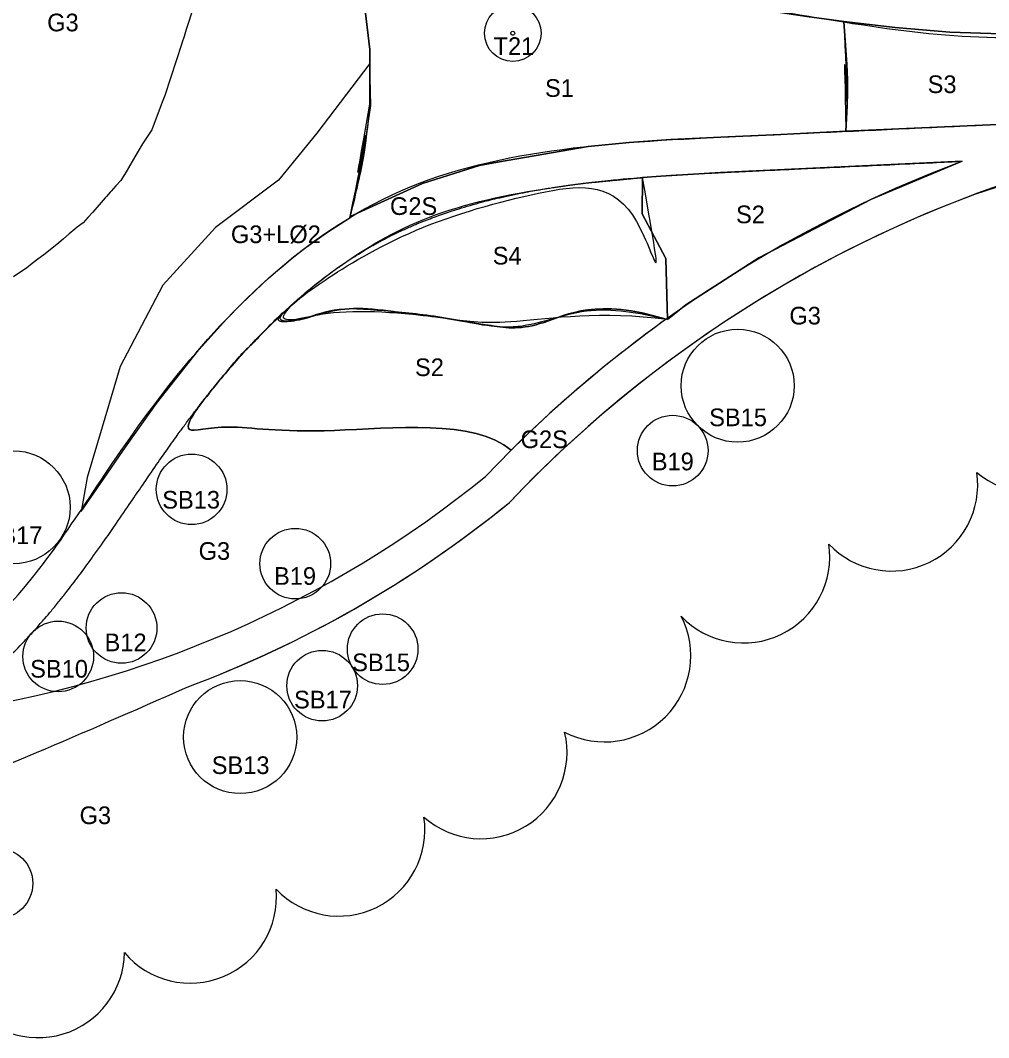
# Model space of a CAD drawing. Extents: x 0 to 512122, y 0 to 6212554.
# Drawn here: x 511501.5 to 511570.1, y 6211310.9 to 6211382.9 of the extents above; entities that cross this region are included whole.
import ezdxf

# ---------------------------------------------------------------- set-up
doc = ezdxf.new("R2010")
doc.units = 0
for name, color, linetype in [('_G3S_Slået græsser', 7, 'Continuous'), ('_LØ2', 7, 'Continuous'), ('_Paths', 7, 'Continuous'), ('_S1_rabarber', 7, 'Continuous'), ('_S2_skovjorbær', 7, 'Continuous'), ('_S3_Mynte', 7, 'Continuous'), ('_S4_Løvstikke', 7, 'Continuous'), ('_Spredmingskorridor_hatch', 7, 'Continuous'), ('Clouds', 7, 'Continuous'), ('Skel', 7, 'Continuous'), ('TV_U_AFM_Symbl_Gul', 7, 'Continuous'), ('TV_U_LYS_Mastenummer', 7, 'Continuous'), ('TV_U_LYS_Nyx330-Trafiksti-x2', 7, 'Continuous')]:
    doc.layers.add(name, color=color, linetype=linetype)

# ---------------------------------------------------------------- blocks, each defined once
blk = doc.blocks.new('SOLITAIRE TREES')
at = {"layer": 'Skel'}
for radius in [2, 0.141]:
    blk.add_circle((0, 0), radius, dxfattribs=at)

msp = doc.modelspace()

# ---------------------------------------------------------------- linework, layer by layer
at = {"layer": '_G3S_Slået græsser'}
msp.add_open_spline([(511577.95, 6211373.42), (511575.884, 6211372.856), (511571.072, 6211371.35), (511569.062, 6211370.609), (511577.95, 6211373.42), (511569.062, 6211370.609)], degree=3, dxfattribs=at)
at = {"layer": '_LØ2'}
msp.add_lwpolyline([(511526.26, 6211379.864), (511522.52, 6211374.951), (511519.801, 6211371.62), (511515.336, 6211368.267), (511511.61, 6211364.186), (511508.601, 6211358.419), (511507.324, 6211354.123), (511506.248, 6211350.554), (511505.835, 6211348.17), (511507.421, 6211350.442), (511508.802, 6211352.488), (511511.168, 6211355.815), (511514.162, 6211359.603), (511516.125, 6211361.774), (511517.188, 6211362.853), (511519.105, 6211364.695), (511520.865, 6211366.19), (511521.56, 6211366.728), (511523.262, 6211367.941), (511524.852, 6211368.956), (511525.365, 6211371.222), (511525.832, 6211373.576), (511526.323, 6211376.898)], close=True, dxfattribs=at)
at = {"layer": '_Paths'}
for centre, radius, start, end in [((511599.913, 6211288.279), 87.92, 104.34684, 136.49474), ((511599.913, 6211288.279), 90.42, 110.54211, 136.3929), ((511599.913, 6211288.279), 87.92, 110.54211, 136.3929), ((511599.913, 6211288.279), 87.92, 110.54211, 136.3929), ((511485.308, 6211411.031), 77.851, 278.00491, 309.13245), ((511485.308, 6211411.031), 80.351, 290.31586, 309.24725), ((511485.308, 6211411.031), 80.351, 290.31926, 309.13245)]:
    msp.add_arc(centre, radius, start, end, dxfattribs=at)
for points in [[(511496.284, 6211337.238), (511497.181, 6211337.983), (511503.211, 6211343.318), (511510.408, 6211356.244), (511526.967, 6211373.541), (511552.416, 6211374.723), (511569.62, 6211375.512), (511577.558, 6211375.876)], [(511496.15, 6211333.938), (511496.382, 6211334.119), (511496.614, 6211334.301), (511497.277, 6211334.827), (511497.707, 6211335.177), (511498.56, 6211335.891), (511498.983, 6211336.255), (511499.609, 6211336.816), (511499.816, 6211337.005), (511500.125, 6211337.293), (511500.227, 6211337.39), (511500.38, 6211337.535), (511500.431, 6211337.584), (511500.533, 6211337.682), (511500.583, 6211337.731), (511501.039, 6211338.174), (511501.432, 6211338.575), (511502.2, 6211339.389), (511502.574, 6211339.802), (511503.305, 6211340.639), (511503.662, 6211341.062), (511504.36, 6211341.916), (511504.702, 6211342.347), (511505.71, 6211343.65), (511506.356, 6211344.531), (511507.619, 6211346.304), (511508.235, 6211347.195), (511509.454, 6211348.976), (511510.058, 6211349.864), (511511.269, 6211351.627), (511511.876, 6211352.5), (511512.804, 6211353.79), (511513.115, 6211354.216), (511513.746, 6211355.061), (511514.065, 6211355.48), (511515.037, 6211356.725), (511515.702, 6211357.539), (511517.067, 6211359.122), (511517.767, 6211359.891), (511519.202, 6211361.371), (511519.937, 6211362.082), (511521.44, 6211363.435), (511522.209, 6211364.077), (511523.78, 6211365.279), (511524.583, 6211365.839), (511525.812, 6211366.612), (511526.226, 6211366.858), (511526.749, 6211367.15), (511526.853, 6211367.208), (511527.011, 6211367.293), (511527.064, 6211367.322), (511527.169, 6211367.378), (511527.222, 6211367.406), (511527.486, 6211367.545), (511527.7, 6211367.653), (511528.344, 6211367.971), (511528.781, 6211368.172), (511529.665, 6211368.555), (511530.114, 6211368.736), (511531.477, 6211369.251), (511532.41, 6211369.557), (511534.317, 6211370.104), (511535.292, 6211370.343), (511537.278, 6211370.766), (511538.289, 6211370.949), (511540.341, 6211371.267), (511541.381, 6211371.402), (511543.485, 6211371.635), (511544.548, 6211371.733), (511546.689, 6211371.901), (511547.767, 6211371.972), (511549.933, 6211372.096), (511551.02, 6211372.151), (511552.38, 6211372.215), (511552.652, 6211372.228), (511553.061, 6211372.247), (511553.197, 6211372.253), (511553.469, 6211372.266), (511553.605, 6211372.272), (511554.285, 6211372.304), (511555.913, 6211372.38), (511557.532, 6211372.455), (511560.757, 6211372.604), (511562.891, 6211372.704), (511566.075, 6211372.852), (511567.131, 6211372.901), (511568.185, 6211372.95)], [(511422.936, 6211366.106), (511424.117, 6211362.932), (511427.915, 6211354.799), (511434.078, 6211340.703), (511442.957, 6211324.941), (511459.145, 6211317.324), (511475.029, 6211321.473), (511492.664, 6211326.687), (511505.824, 6211332.405), (511513.21, 6211335.68)]]:
    msp.add_open_spline(points, degree=3, dxfattribs=at)
at = {"layer": '_S1_rabarber'}
for points in [[(511526.256, 6211376.989), (511526.268, 6211380.857), (511525.432, 6211387.792), (511524.381, 6211399.347), (511527.219, 6211394.835), (511529.727, 6211391.636), (511532.584, 6211388.932), (511535.615, 6211387.042), (511537.588, 6211386.323), (511540.138, 6211385.706), (511542.64, 6211385.314), (511549.961, 6211384.291), (511557.192, 6211383.208), (511559.801, 6211382.854)], [(511559.801, 6211382.854), (511557.192, 6211383.208), (511549.961, 6211384.291), (511542.64, 6211385.314), (511540.138, 6211385.706), (511537.588, 6211386.323), (511535.615, 6211387.042), (511532.584, 6211388.932), (511529.727, 6211391.636), (511527.219, 6211394.835), (511524.381, 6211399.347), (511525.432, 6211387.792), (511526.268, 6211380.857), (511526.256, 6211376.989)], [(511559.953, 6211375.077), (511555.358, 6211374.856), (511551.59, 6211374.681), (511547.568, 6211374.486), (511544.625, 6211374.289), (511541.716, 6211373.999), (511535.288, 6211372.879), (511534.023, 6211372.647), (511529.982, 6211371.369), (511524.867, 6211369.041)], [(511524.867, 6211369.041), (511529.982, 6211371.369), (511534.023, 6211372.647), (511535.288, 6211372.879), (511541.716, 6211373.999), (511544.625, 6211374.289), (511547.568, 6211374.486), (511551.59, 6211374.681), (511555.358, 6211374.856), (511559.953, 6211375.077)]]:
    msp.add_lwpolyline(points, dxfattribs=at)
for points in [[(511559.801, 6211382.854), (511560.066, 6211377.754), (511559.953, 6211375.077), (511559.801, 6211382.854), (511559.953, 6211375.077)], [(511559.953, 6211375.077), (511560.005, 6211375.969), (511560.157, 6211378.563), (511559.942, 6211381.154), (511559.801, 6211382.854)], [(511524.867, 6211369.041), (511525.961, 6211374.32), (511526.256, 6211376.989), (511524.867, 6211369.041), (511526.256, 6211376.989)], [(511526.256, 6211376.989), (511526.172, 6211376.098), (511525.917, 6211373.415), (511525.287, 6211370.792), (511524.867, 6211369.041)]]:
    msp.add_open_spline(points, degree=3, dxfattribs=at)
at = {"layer": '_S2_skovjorbær'}
msp.add_line((511547.231, 6211361.766), (511547.231, 6211361.766), dxfattribs=at)
msp.add_lwpolyline([(511547.214, 6211366.059), (511545.542, 6211369.221), (511545.547, 6211371.8), (511546.852, 6211371.901), (511551.085, 6211372.149), (511568.185, 6211372.95), (511561.763, 6211370.274), (511553.78, 6211366.124), (511548.622, 6211362.784), (511547.326, 6211361.742), (511547.214, 6211366.059)], dxfattribs=at)
msp.add_lwpolyline([(511547.326, 6211361.742), (511548.622, 6211362.784), (511553.78, 6211366.124), (511561.763, 6211370.274), (511568.185, 6211372.95), (511551.085, 6211372.149), (511546.852, 6211371.901), (511545.547, 6211371.8), (511545.542, 6211369.221), (511547.214, 6211366.059)], close=True, dxfattribs=at)
msp.add_arc((511599.913, 6211288.279), 90.42, 125.63628, 134.75422, dxfattribs=at)
msp.add_arc((511599.913, 6211288.279), 90.42, 125.63628, 134.75422, dxfattribs=at)
for points in [[(511547.231, 6211361.766), (511542.358, 6211363.29), (511538.022, 6211360.885), (511534.945, 6211361.269), (511531.26, 6211361.927), (511528.768, 6211362.168), (511525.608, 6211362.662), (511523.32, 6211362.361), (511521.384, 6211361.687), (511519.995, 6211361.557), (511519.62, 6211361.679), (511519.945, 6211362.066)], [(511519.945, 6211362.066), (511519.62, 6211361.679), (511519.995, 6211361.557), (511521.384, 6211361.687), (511523.32, 6211362.361), (511525.608, 6211362.662), (511528.768, 6211362.168), (511531.26, 6211361.927), (511534.945, 6211361.269), (511538.022, 6211360.885), (511542.358, 6211363.29), (511547.231, 6211361.766)], [(511519.945, 6211362.066), (511519.1, 6211361.199), (511518.127, 6211360.26), (511517.701, 6211359.775), (511517.257, 6211359.421), (511516.044, 6211357.948), (511515.353, 6211357.112), (511515.015, 6211356.704), (511514.781, 6211356.368), (511514.137, 6211355.639), (511512.739, 6211353.417), (511515.839, 6211354.508), (511521.755, 6211353.372), (511533.688, 6211354.725), (511536.251, 6211352.489)], [(511536.251, 6211352.489), (511533.688, 6211354.725), (511521.755, 6211353.372), (511515.839, 6211354.508), (511512.739, 6211353.417), (511514.137, 6211355.639), (511514.781, 6211356.368), (511515.015, 6211356.704), (511515.353, 6211357.112), (511516.044, 6211357.948), (511517.257, 6211359.421), (511517.701, 6211359.775), (511518.127, 6211360.26), (511519.1, 6211361.199), (511519.945, 6211362.066)]]:
    msp.add_open_spline(points, degree=3, dxfattribs=at)
at = {"layer": '_S3_Mynte'}
msp.add_lwpolyline([(511573.351, 6211381.998), (511570.939, 6211381.975), (511567.316, 6211382.1), (511563.441, 6211382.432), (511559.802, 6211382.849), (511560.022, 6211379.806), (511560.059, 6211378.724), (511560.065, 6211377.836), (511560.047, 6211376.868), (511559.954, 6211375.075), (511571.776, 6211375.611)], dxfattribs=at)
msp.add_lwpolyline([(511571.776, 6211375.611), (511559.954, 6211375.075), (511560.047, 6211376.868), (511560.065, 6211377.836), (511560.059, 6211378.724), (511560.022, 6211379.806), (511559.802, 6211382.849), (511563.441, 6211382.432), (511567.316, 6211382.1), (511570.939, 6211381.975), (511573.351, 6211381.998)], close=True, dxfattribs=at)
at = {"layer": '_S4_Løvstikke'}
for points in [[(511545.547, 6211371.804), (511545.542, 6211369.224), (511547.214, 6211366.062)], [(511545.547, 6211371.8), (511545.542, 6211369.224), (511547.214, 6211366.062), (511547.326, 6211361.745)], [(511547.214, 6211366.062), (511547.326, 6211361.745)]]:
    msp.add_lwpolyline(points, dxfattribs=at)
for points, degree in [([(511547.326, 6211361.745), (511542.618, 6211362.374), (511535.415, 6211361.239), (511532.11, 6211361.782), (511527.621, 6211362.325), (511523.379, 6211362.325), (511521.06, 6211361.683), (511519.793, 6211361.702), (511520.66, 6211362.734), (511522.197, 6211364.046), (511529.106, 6211368.337), (511538.627, 6211371.004), (511545.552, 6211371.801), (511547.326, 6211361.745), (511545.552, 6211371.801)], 3), ([(511538.627, 6211371.004), (511540.912, 6211371.354), (511543.23, 6211371.577), (511545.547, 6211371.8)], 2), ([(511547.326, 6211361.745), (511545.755, 6211362.096), (511541.773, 6211362.987), (511536.719, 6211360.638), (511531.712, 6211361.972), (511527.809, 6211362.298), (511523.743, 6211362.693), (511521.752, 6211361.708), (511519.198, 6211361.456), (511521.025, 6211363.052), (511523.443, 6211365.161), (511529.589, 6211369.132), (511535.383, 6211370.506), (511538.627, 6211371.004)], 3)]:
    msp.add_open_spline(points, degree=degree, dxfattribs=at)
at = {"layer": '_Spredmingskorridor_hatch'}
msp.add_open_spline([(511467.291, 6211448.868), (511473.268, 6211448.326), (511486.519, 6211446.703), (511493.234, 6211420.769), (511520.952, 6211413.243), (511528.733, 6211386.924), (511552.285, 6211384.428), (511571.21, 6211380.366), (511589.487, 6211384.409), (511596.578, 6211388.532), (511598.184, 6211389.583)], degree=3, dxfattribs=at)
at = {"layer": 'Clouds'}
for centre, start, end in [((511573.169, 6211355.57), 229.63626, 14.63626), ((511563.182, 6211350.04), 223.30717, 8.30717), ((511552.71, 6211344.952), 223.52549, 8.52549), ((511542.872, 6211337.943), 242.40351, 27.40351), ((511534.119, 6211331.095), 228.67799, 13.67799), ((511524.057, 6211325.614), 223.47784, 8.47784), ((511513.555, 6211320.868), 220.16545, 5.16545), ((511502.794, 6211317.009), 214.28131, 359.28131)]:
    msp.add_arc(centre, 6.1, start, end, dxfattribs=at)
at = {"layer": 'TV_U_LYS_Mastenummer'}
for centre, radius in [((511552.291, 6211357.065), 4), ((511552.291, 6211357.065), 4), ((511547.695, 6211352.469), 2.5), ((511547.695, 6211352.469), 2.5), ((511501.05, 6211348.456), 4), ((511513.649, 6211349.728), 2.5), ((511520.982, 6211344.465), 2.5), ((511508.686, 6211339.912), 2.5), ((511504.204, 6211337.898), 2.5), ((511504.204, 6211337.898), 2.5), ((511527.168, 6211338.414), 2.5), ((511527.168, 6211338.414), 2.5), ((511522.887, 6211335.828), 2.5), ((511522.887, 6211335.828), 2.5), ((511517.083, 6211332.189), 4), ((511499.901, 6211321.829), 2.5)]:
    msp.add_circle(centre, radius, dxfattribs=at)
at = {"layer": 'TV_U_LYS_Nyx330-Trafiksti-x2'}
msp.add_lwpolyline([(511513.788, 6211383.886), (511513.427, 6211382.772), (511513.269, 6211382.284), (511513.111, 6211381.797), (511512.953, 6211381.309), (511512.946, 6211381.287), (511511.755, 6211377.61), (511511.604, 6211377.244), (511511.565, 6211377.146), (511511.49, 6211376.955), (511510.824, 6211375.173), (511510.548, 6211374.748), (511510.271, 6211374.324), (511510.181, 6211374.185), (511510.023, 6211373.941), (511509.996, 6211373.899), (511509.785, 6211373.557), (511508.916, 6211372.045), (511508.902, 6211372.022), (511508.642, 6211371.595), (511508.287, 6211371.223), (511507.952, 6211370.839), (511507.885, 6211370.762), (511507.619, 6211370.455), (511507.532, 6211370.359), (511506.645, 6211369.353), (511506.311, 6211368.975), (511505.978, 6211368.597), (511505.54, 6211368.289), (511505.386, 6211368.155), (511504.98, 6211367.804), (511504.59, 6211367.466), (511504.235, 6211367.158), (511504.218, 6211367.145), (511503.176, 6211366.333), (511502.773, 6211366.019), (511502.37, 6211365.705), (511501.968, 6211365.391), (511501.712, 6211365.222), (511501.049, 6211364.762)], dxfattribs=at)

# ---------------------------------------------------------------- block references
at = {"layer": 'Skel'}
msp.add_blockref('SOLITAIRE TREES', (511536.374, 6211382.017), dxfattribs=at)

# ---------------------------------------------------------------- texts
at = {"layer": 'TV_U_AFM_Symbl_Gul'}
for s, p in [('G3', (511503.424, 6211382.153)), ('T21', (511535.016, 6211380.482)), ('S1', (511538.656, 6211377.513)), ('S3', (511565.738, 6211377.781)), ('G2S', (511527.686, 6211369.153)), ('S2', (511552.178, 6211368.567)), ('G3+LØ2', (511516.427, 6211367.159)), ('S4', (511534.957, 6211365.644)), ('G3', (511555.953, 6211361.399)), ('S2', (511529.456, 6211357.744)), ('SB15', (511550.276, 6211354.199)), ('G2S', (511536.931, 6211352.646)), ('B19', (511546.213, 6211351.073)), ('SB13', (511511.568, 6211348.366)), ('SB17', (511498.998, 6211345.85)), ('G3', (511514.142, 6211344.737)), ('B19', (511519.479, 6211342.968)), ('B12', (511507.487, 6211338.266)), ('SB15', (511525.011, 6211336.855)), ('SB10', (511502.222, 6211336.397)), ('SB17', (511520.895, 6211334.218)), ('SB13', (511515.07, 6211329.573)), ('G3', (511505.716, 6211326.027))]:
    msp.add_text(s, height=1.25, dxfattribs=at).set_placement(p)

doc.saveas('drawing.dxf')
